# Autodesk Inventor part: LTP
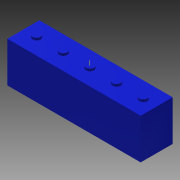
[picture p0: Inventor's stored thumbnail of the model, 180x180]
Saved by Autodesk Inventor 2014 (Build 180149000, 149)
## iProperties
Shininess: 64.0
Length Units: 11272
Angle Units: 11279
Time Units: 11290
Mass Units: 11286
Length Display Precision: 3
Angle Display Precision: 2
Compacted: True
Part Number: LTP
Document SubType Name: Modeling
Created: 2003-10
Designer: brondec
Manufacturer: Standard
Standards Organization: Custom
Density: 1 g/cm^3
Mass: 1.13797 g
Surface Area: 7.79089 cm^2
Volume: 1.13797 cm^3
Material: Generic
Appearance: Blue - Wall Paint - Glossy
Density: 0.0
Volumn: 0.0
Area: 0.0
PropertySet Name: Model Information
Control State: 0
Master: False
Checked Out: False
Author: brondec
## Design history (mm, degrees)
sketch "Sketch3"
  geometry: L1 (-0.635, -1.651)-(24.359, -1.651); L2 (24.359, -1.651)-(24.359, 4.343); L3 (24.359, 4.343)-(-0.635, 4.343); L4 (-0.635, 4.343)-(-0.635, -1.651); 1 further point
  constraints: 8 end point, 2 parallel, 1 horizontal, 1 perpendicular
  dimensions: "d17" = 5.9944 distance of L3.end L1.start; "d18" = 24.9936 distance of L2.end L3.end; "d19" = 0.635 distance from line of L4 point (0, 0); "d20" = 1.651 distance from line of point (0, 0) L1
extrude "Extrusion1" new body sketch "Sketch3" distance "d5" = 7.5692; taper "d6" = 0 deg
sketch "Sketch4"
  geometry: L1 (-0.635, -1.651)-(-0.635, 4.343) reference; L2 (11.859, 1.346)-(16.863, 1.346); L3 (16.863, 1.346)-(21.866, 1.346); L4 (6.855, 1.346)-(1.851, 1.346); L5 (11.859, 1.346)-(6.855, 1.346); C1 r 0.762 at (1.851, 1.346); C2 r 0.762 at (6.855, 1.346); C3 r 0.762 at (11.859, 1.346); C4 r 0.762 at (16.863, 1.346); C5 r 0.762 at (21.866, 1.346); 1 further point
  constraints: 8 end point, 5 centre point, 5 collinear, 4 equal radius, 2 horizontal, 1 horizontal alignment, 1 midpoint
  dimensions: "d14" = 2.48617 distance from line of L1 L4.end; "d15" = 1.524 diameter of C1; "d16" = 5.0038 distance of L4.start L4.end
extrude "Extrusion2" join sketch "Sketch4" distance "d12" = 0.4318; taper "d13" = 0 deg
workaxis "Work Axis1"
body "Solid1"
